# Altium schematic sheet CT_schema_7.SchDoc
size 274 x 160 mm
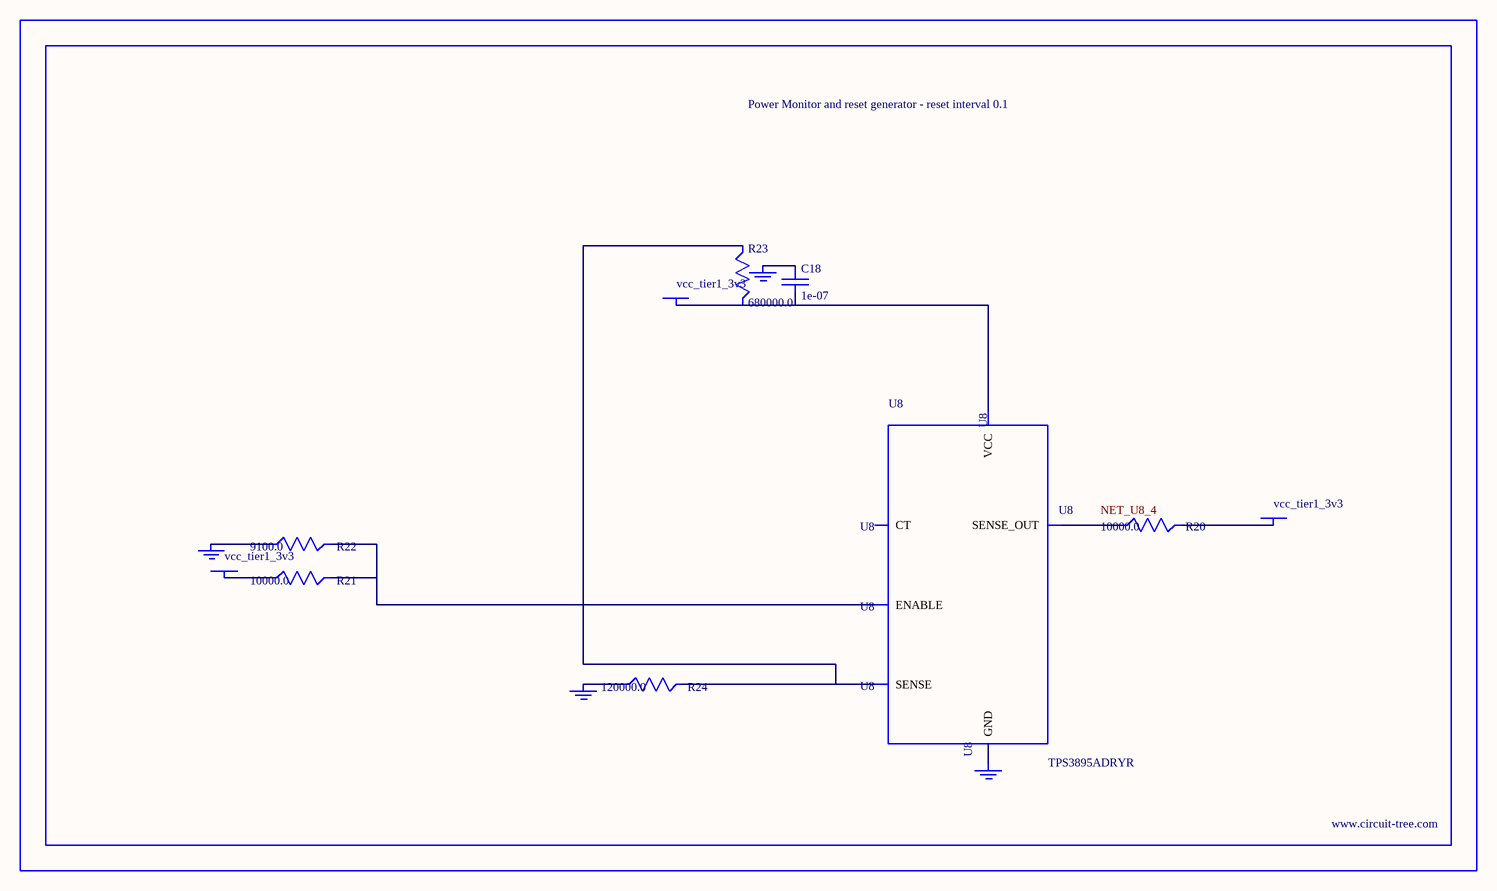
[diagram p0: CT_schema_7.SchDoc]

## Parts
BORDER6  (no value)
C18  1e-07  [C0402]
GND_INSTANCE_6_0  (no value)
GND_INSTANCE_6_1  (no value)
GND_INSTANCE_6_2  (no value)
GND_INSTANCE_6_3  (no value)
POWER_INSTANCE_6_0  vcc_tier1_3v3
POWER_INSTANCE_6_1  vcc_tier1_3v3
POWER_INSTANCE_6_2  vcc_tier1_3v3
R20  10000.0  [R0603]
R21  10000.0  [R0603]
R22  9100.0  [R0603]
R23  680000.0  [R0603]
R24  120000.0  [R0603]
U8  TPS3895ADRYR  [SON-6]

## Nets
NetC18_1: C18.1 GND_INSTANCE_6_2.0(GND)
NetC18_2: C18.2 POWER_INSTANCE_6_2.0(PWR) R23.2 U8.6(VCC)
NetGND_INSTANCE_6_0_0: GND_INSTANCE_6_0.0(GND) R22.1
NetGND_INSTANCE_6_1_0: GND_INSTANCE_6_1.0(GND) R24.1
NetGND_INSTANCE_6_3_0: GND_INSTANCE_6_3.0(GND) U8.2(GND)
NetPOWER_INSTANCE_6_0_0: POWER_INSTANCE_6_0.0(PWR) R21.1
NetPOWER_INSTANCE_6_1_0: POWER_INSTANCE_6_1.0(PWR) R20.2
NetR20_1: R20.1 U8.4(SENSE_OUT)
NetR21_2: R21.2 R22.2 U8.1(ENABLE)
NetR23_1: R23.1 R24.2 U8.3(SENSE)

Not connected (* = marked no-connect by the designer): U8 5(CT)

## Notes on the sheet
- Labels drawn without touching a wire or pin: NET_U8_4

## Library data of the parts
BORDER6 = BORDER_PAGE6
C18 = C0402C104K3RACTU
GND_INSTANCE_6_0-GND_INSTANCE_6_3 = GND
POWER_INSTANCE_6_0-POWER_INSTANCE_6_2 = PWR
R20 R21 = RC0603JR-0710KL
R22 = RC0603JR-079K1L
R23 = RC0603JR-07680KL
R24 = RC0603JR-07120KL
